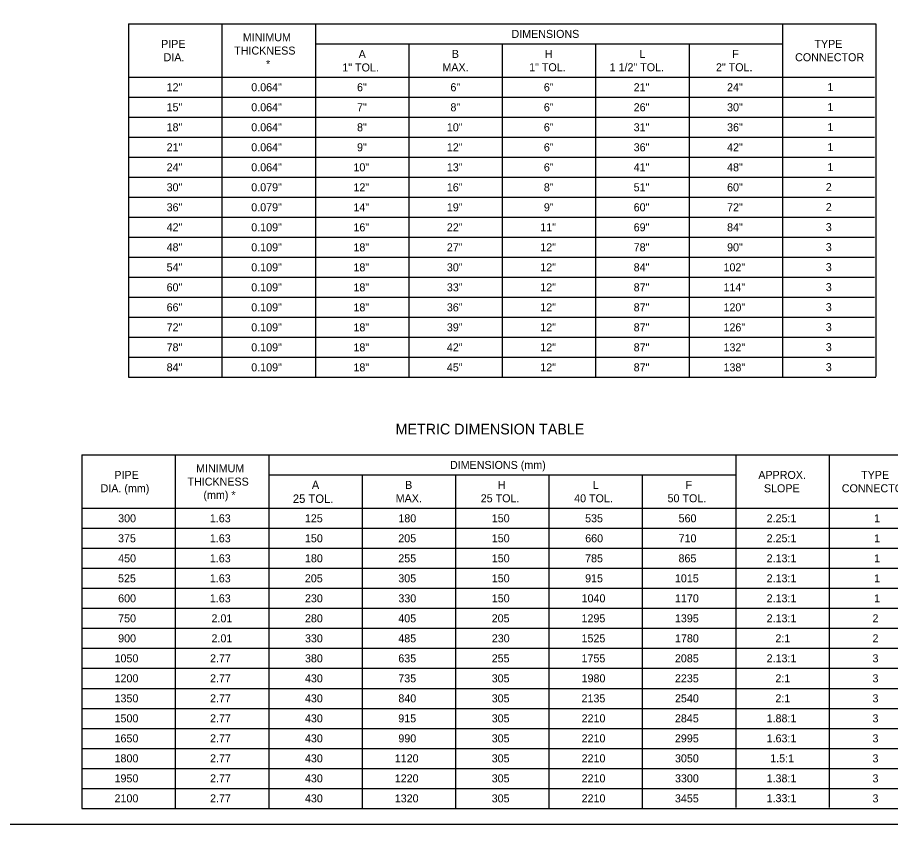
# Model space of a CAD drawing. Extents: x 49991.4 to 50021, y 49987.6 to 50011.4.
# Drawn here: x 50006.92 to 50013.46, y 49987.8 to 49993.85 of the extents above; entities that cross this region are included whole.
import ezdxf

# ---------------------------------------------------------------- set-up
doc = ezdxf.new("R2010")
doc.units = 0
doc.layers.add('Level 1', color=7, linetype='Continuous')
doc.layers.add('Level 2', color=7, linetype='Continuous')

msp = doc.modelspace()

# ---------------------------------------------------------------- linework, layer by layer
at = {"layer": 'Level 1'}
msp.add_lwpolyline([(49999.3835, 49998.9992), (50016.7501, 49998.9992), (50016.7501, 49987.7988), (49999.3835, 49987.7988)], close=True, dxfattribs=at)
at = {"layer": 'Level 2'}
for p, q in [((50007.7477, 49993.802), (50007.7477, 49991.152)), ((50007.7477, 49993.802), (50013.3477, 49993.802)), ((50008.4477, 49993.802), (50008.4477, 49991.152)), ((50009.1477, 49993.802), (50009.1477, 49991.152)), ((50012.6477, 49993.802), (50012.6477, 49991.1586)), ((50013.3477, 49993.802), (50013.3477, 49991.1586)), ((50009.1477, 49993.652), (50012.6477, 49993.652)), ((50009.8477, 49993.652), (50009.8477, 49991.152)), ((50010.5477, 49993.652), (50010.5477, 49991.152)), ((50011.2477, 49993.652), (50011.2477, 49991.152)), ((50011.9477, 49993.652), (50011.9477, 49991.152)), ((50007.7477, 49993.402), (50013.3377, 49993.402)), ((50007.7477, 49993.252), (50013.3377, 49993.252)), ((50007.7477, 49993.102), (50013.3377, 49993.102)), ((50007.7477, 49992.952), (50013.3377, 49992.952)), ((50007.7477, 49992.802), (50013.3377, 49992.802)), ((50007.7477, 49992.652), (50013.3377, 49992.652)), ((50007.7477, 49992.502), (50013.3377, 49992.502)), ((50007.7477, 49992.352), (50013.3377, 49992.352)), ((50007.7477, 49992.202), (50013.3377, 49992.202)), ((50007.7477, 49992.052), (50013.3377, 49992.052)), ((50007.7477, 49991.902), (50013.3377, 49991.902)), ((50007.7477, 49991.752), (50013.3377, 49991.752)), ((50007.7477, 49991.602), (50013.3377, 49991.602)), ((50007.7477, 49991.452), (50013.3377, 49991.452)), ((50007.7477, 49991.302), (50013.3377, 49991.302)), ((50007.7477, 49991.152), (50013.3477, 49991.152)), ((50007.3977, 49990.5701), (50007.3977, 49987.9201)), ((50007.3977, 49990.5701), (50013.6977, 49990.5701)), ((50008.0977, 49990.5701), (50008.0977, 49987.9201)), ((50008.7977, 49990.5701), (50008.7977, 49987.9201)), ((50012.2977, 49990.5701), (50012.2977, 49987.9267)), ((50012.9977, 49990.5701), (50012.9977, 49987.9267)), ((50008.7977, 49990.4201), (50012.2977, 49990.4201)), ((50009.4977, 49990.4201), (50009.4977, 49987.9201)), ((50010.1977, 49990.4201), (50010.1977, 49987.9201)), ((50010.8977, 49990.4201), (50010.8977, 49987.9201)), ((50011.5977, 49990.4201), (50011.5977, 49987.9201)), ((50007.3977, 49990.1701), (50013.6977, 49990.1701)), ((50007.3977, 49990.0201), (50013.6977, 49990.0201)), ((50007.3977, 49989.8701), (50013.6977, 49989.8701)), ((50007.3977, 49989.7201), (50013.6977, 49989.7201)), ((50007.3977, 49989.5701), (50013.6977, 49989.5701)), ((50007.3977, 49989.4201), (50013.6977, 49989.4201)), ((50007.3977, 49989.2701), (50013.6977, 49989.2701)), ((50007.3977, 49989.1201), (50013.6977, 49989.1201)), ((50007.3977, 49988.9701), (50013.6977, 49988.9701)), ((50007.3977, 49988.8201), (50013.6977, 49988.8201)), ((50007.3977, 49988.6701), (50013.6977, 49988.6701)), ((50007.3977, 49988.5201), (50013.6977, 49988.5201)), ((50007.3977, 49988.3701), (50013.6977, 49988.3701)), ((50007.3977, 49988.2201), (50013.6977, 49988.2201)), ((50007.3977, 49988.0701), (50013.6977, 49988.0701)), ((50007.3977, 49987.9201), (50013.6977, 49987.9201))]:
    msp.add_line(p, q, dxfattribs=at)

# ---------------------------------------------------------------- texts
for s, height, p in [('MINIMUM', 0.06, (50008.6036, 49993.672)), ('DIMENSIONS', 0.06, (50010.6172, 49993.697)), ('PIPE', 0.06, (50007.9914, 49993.622)), ('THICKNESS', 0.06, (50008.5392, 49993.572)), ('TYPE', 0.06, (50012.8875, 49993.622)), ('DIA.', 0.06, (50008.0103, 49993.522)), ('A', 0.06, (50009.4719, 49993.5455)), ('B', 0.06, (50010.17, 49993.547)), ('H', 0.06, (50010.8657, 49993.547)), ('L', 0.06, (50011.5765, 49993.547)), ('F', 0.06, (50012.2715, 49993.547)), ('CONNECTOR', 0.06, (50012.7426, 49993.522)), ('*', 0.06, (50008.7778, 49993.472)), ('1" TOL.', 0.06, (50009.3495, 49993.4455)), ('MAX.', 0.06, (50010.0995, 49993.447)), ('1" TOL.', 0.06, (50010.7495, 49993.447)), ('1 1/2" TOL.', 0.06, (50011.3527, 49993.447)), ('2" TOL.', 0.06, (50012.1495, 49993.447)), ('12"', 0.06, (50008.0328, 49993.297)), ('0.064"', 0.06, (50008.6671, 49993.297)), ('6"', 0.06, (50009.4597, 49993.297)), ('6"', 0.06, (50010.1597, 49993.297)), ('6"', 0.06, (50010.8597, 49993.297)), ('21"', 0.06, (50011.5328, 49993.297)), ('24"', 0.06, (50012.2328, 49993.297)), ('1', 0.06, (50012.9847, 49993.2984)), ('15"', 0.06, (50008.0328, 49993.147)), ('0.064"', 0.06, (50008.6671, 49993.147)), ('7"', 0.06, (50009.4597, 49993.147)), ('8"', 0.06, (50010.1597, 49993.147)), ('6"', 0.06, (50010.8597, 49993.147)), ('26"', 0.06, (50011.5328, 49993.147)), ('30"', 0.06, (50012.2328, 49993.147)), ('1', 0.06, (50012.9847, 49993.1484)), ('18"', 0.06, (50008.0328, 49992.997)), ('0.064"', 0.06, (50008.6671, 49992.997)), ('8"', 0.06, (50009.4597, 49992.997)), ('10"', 0.06, (50010.1328, 49992.997)), ('6"', 0.06, (50010.8597, 49992.997)), ('31"', 0.06, (50011.5328, 49992.997)), ('36"', 0.06, (50012.2328, 49992.997)), ('1', 0.06, (50012.9847, 49992.9984)), ('21"', 0.06, (50008.0328, 49992.847)), ('0.064"', 0.06, (50008.6671, 49992.847)), ('9"', 0.06, (50009.4597, 49992.847)), ('12"', 0.06, (50010.1328, 49992.847)), ('6"', 0.06, (50010.8597, 49992.847)), ('36"', 0.06, (50011.5328, 49992.847)), ('42"', 0.06, (50012.2328, 49992.847)), ('1', 0.06, (50012.9847, 49992.8484)), ('24"', 0.06, (50008.0328, 49992.697)), ('0.064"', 0.06, (50008.6671, 49992.697)), ('10"', 0.06, (50009.4328, 49992.697)), ('13"', 0.06, (50010.1328, 49992.697)), ('6"', 0.06, (50010.8597, 49992.697)), ('41"', 0.06, (50011.5328, 49992.697)), ('48"', 0.06, (50012.2328, 49992.697)), ('1', 0.06, (50012.9847, 49992.6984)), ('30"', 0.06, (50008.0328, 49992.547)), ('0.079"', 0.06, (50008.6671, 49992.547)), ('12"', 0.06, (50009.4328, 49992.547)), ('16"', 0.06, (50010.1328, 49992.547)), ('8"', 0.06, (50010.8597, 49992.547)), ('51"', 0.06, (50011.5328, 49992.547)), ('60"', 0.06, (50012.2328, 49992.547)), ('2', 0.06, (50012.9725, 49992.5484)), ('36"', 0.06, (50008.0328, 49992.397)), ('0.079"', 0.06, (50008.6671, 49992.397)), ('14"', 0.06, (50009.4328, 49992.397)), ('19"', 0.06, (50010.1328, 49992.397)), ('9"', 0.06, (50010.8597, 49992.397)), ('60"', 0.06, (50011.5328, 49992.397)), ('72"', 0.06, (50012.2328, 49992.397)), ('2', 0.06, (50012.9725, 49992.3984)), ('42"', 0.06, (50008.0328, 49992.247)), ('0.109"', 0.06, (50008.6671, 49992.247)), ('16"', 0.06, (50009.4328, 49992.247)), ('22"', 0.06, (50010.1328, 49992.247)), ('11"', 0.06, (50010.8328, 49992.247)), ('69"', 0.06, (50011.5328, 49992.247)), ('84"', 0.06, (50012.2328, 49992.247)), ('3', 0.06, (50012.9725, 49992.2484)), ('48"', 0.06, (50008.0328, 49992.097)), ('0.109"', 0.06, (50008.6671, 49992.097)), ('18"', 0.06, (50009.4328, 49992.097)), ('27"', 0.06, (50010.1328, 49992.097)), ('12"', 0.06, (50010.8328, 49992.097)), ('78"', 0.06, (50011.5328, 49992.097)), ('90"', 0.06, (50012.2328, 49992.097)), ('3', 0.06, (50012.9725, 49992.0984)), ('54"', 0.06, (50008.0328, 49991.947)), ('0.109"', 0.06, (50008.6671, 49991.947)), ('18"', 0.06, (50009.4328, 49991.947)), ('30"', 0.06, (50010.1328, 49991.947)), ('12"', 0.06, (50010.8328, 49991.947)), ('84"', 0.06, (50011.5328, 49991.947)), ('102"', 0.06, (50012.2059, 49991.947)), ('3', 0.06, (50012.9725, 49991.9484)), ('60"', 0.06, (50008.0328, 49991.797)), ('0.109"', 0.06, (50008.6671, 49991.797)), ('18"', 0.06, (50009.4328, 49991.797)), ('33"', 0.06, (50010.1328, 49991.797)), ('12"', 0.06, (50010.8328, 49991.797)), ('87"', 0.06, (50011.5328, 49991.797)), ('114"', 0.06, (50012.2059, 49991.797)), ('3', 0.06, (50012.9725, 49991.7984)), ('66"', 0.06, (50008.0328, 49991.647)), ('0.109"', 0.06, (50008.6671, 49991.647)), ('18"', 0.06, (50009.4328, 49991.647)), ('36"', 0.06, (50010.1328, 49991.647)), ('12"', 0.06, (50010.8328, 49991.647)), ('87"', 0.06, (50011.5328, 49991.647)), ('120"', 0.06, (50012.2059, 49991.647)), ('3', 0.06, (50012.9725, 49991.6484)), ('72"', 0.06, (50008.0328, 49991.497)), ('0.109"', 0.06, (50008.6671, 49991.497)), ('18"', 0.06, (50009.4328, 49991.497)), ('39"', 0.06, (50010.1328, 49991.497)), ('12"', 0.06, (50010.8328, 49991.497)), ('87"', 0.06, (50011.5328, 49991.497)), ('126"', 0.06, (50012.2059, 49991.497)), ('3', 0.06, (50012.9725, 49991.4984)), ('78"', 0.06, (50008.0328, 49991.347)), ('0.109"', 0.06, (50008.6671, 49991.347)), ('18"', 0.06, (50009.4328, 49991.347)), ('42"', 0.06, (50010.1328, 49991.347)), ('12"', 0.06, (50010.8328, 49991.347)), ('87"', 0.06, (50011.5328, 49991.347)), ('132"', 0.06, (50012.2059, 49991.347)), ('3', 0.06, (50012.9725, 49991.3484)), ('84"', 0.06, (50008.0328, 49991.197)), ('0.109"', 0.06, (50008.6671, 49991.197)), ('18"', 0.06, (50009.4328, 49991.197)), ('45"', 0.06, (50010.1328, 49991.197)), ('12"', 0.06, (50010.8328, 49991.197)), ('87"', 0.06, (50011.5328, 49991.197)), ('138"', 0.06, (50012.2059, 49991.197)), ('3', 0.06, (50012.9725, 49991.1984)), ('METRIC DIMENSION TABLE', 0.08, (50009.7483, 49990.7242)), ('MINIMUM', 0.06, (50008.2536, 49990.4401)), ('DIMENSIONS (mm)', 0.06, (50010.1563, 49990.4651)), ('PIPE', 0.06, (50007.6414, 49990.3901)), ('APPROX.', 0.06, (50012.4669, 49990.3901)), ('TYPE', 0.06, (50013.2375, 49990.3901)), ('THICKNESS', 0.06, (50008.1892, 49990.3401)), ('A', 0.063, (50009.1206, 49990.3136)), ('B', 0.06, (50009.82, 49990.3151)), ('H', 0.06, (50010.5157, 49990.3151)), ('L', 0.06, (50011.2265, 49990.3151)), ('F', 0.06, (50011.9215, 49990.3151)), ('DIA. (mm)', 0.06, (50007.538, 49990.2901)), ('(mm) *', 0.06, (50008.3089, 49990.2401)), ('SLOPE', 0.06, (50012.5089, 49990.2901)), ('CONNECTOR', 0.06, (50013.0926, 49990.2901)), ('25 TOL.', 0.063, (50008.9788, 49990.2106)), ('MAX.', 0.06, (50009.7495, 49990.2151)), ('25 TOL.', 0.06, (50010.3868, 49990.2151)), ('40 TOL.', 0.06, (50011.0868, 49990.2151)), ('50 TOL.', 0.06, (50011.7868, 49990.2151)), ('300', 0.06, (50007.6695, 49990.0651)), ('1.63', 0.06, (50008.3568, 49990.0651)), ('125', 0.06, (50009.0689, 49990.0651)), ('180', 0.06, (50009.7695, 49990.0651)), ('150', 0.06, (50010.4695, 49990.0651)), ('535', 0.06, (50011.1689, 49990.0651)), ('560', 0.06, (50011.8695, 49990.0651)), ('2.25:1', 0.06, (50012.5291, 49990.0651)), ('1', 0.06, (50013.3347, 49990.0651)), ('375', 0.06, (50007.6689, 49989.9151)), ('1.63', 0.06, (50008.3568, 49989.9151)), ('150', 0.06, (50009.0695, 49989.9151)), ('205', 0.06, (50009.7689, 49989.9151)), ('150', 0.06, (50010.4695, 49989.9151)), ('660', 0.06, (50011.1695, 49989.9151)), ('710', 0.06, (50011.8695, 49989.9151)), ('2.25:1', 0.06, (50012.5291, 49989.9151)), ('1', 0.06, (50013.3347, 49989.9151)), ('450', 0.06, (50007.6695, 49989.7651)), ('1.63', 0.06, (50008.3568, 49989.7651)), ('180', 0.06, (50009.0695, 49989.7651)), ('255', 0.06, (50009.7689, 49989.7651)), ('150', 0.06, (50010.4695, 49989.7651)), ('785', 0.06, (50011.1689, 49989.7651)), ('865', 0.06, (50011.8689, 49989.7651)), ('2.13:1', 0.06, (50012.5291, 49989.7651)), ('1', 0.06, (50013.3347, 49989.7651)), ('525', 0.06, (50007.6689, 49989.6151)), ('1.63', 0.06, (50008.3568, 49989.6151)), ('205', 0.06, (50009.0689, 49989.6151)), ('305', 0.06, (50009.7689, 49989.6151)), ('150', 0.06, (50010.4695, 49989.6151)), ('915', 0.06, (50011.1689, 49989.6151)), ('1015', 0.06, (50011.842, 49989.6151)), ('2.13:1', 0.06, (50012.5291, 49989.6151)), ('1', 0.06, (50013.3347, 49989.6151)), ('600', 0.06, (50007.6695, 49989.4651)), ('1.63', 0.06, (50008.3568, 49989.4651)), ('230', 0.06, (50009.0695, 49989.4651)), ('330', 0.06, (50009.7695, 49989.4651)), ('150', 0.06, (50010.4695, 49989.4651)), ('1040', 0.06, (50011.1425, 49989.4651)), ('1170', 0.06, (50011.8425, 49989.4651)), ('2.13:1', 0.06, (50012.5291, 49989.4651)), ('1', 0.06, (50013.3347, 49989.4651)), ('750', 0.06, (50007.6695, 49989.3151)), ('2.01', 0.06, (50008.3691, 49989.3151)), ('280', 0.06, (50009.0695, 49989.3151)), ('405', 0.06, (50009.7689, 49989.3151)), ('205', 0.06, (50010.4689, 49989.3151)), ('1295', 0.06, (50011.142, 49989.3151)), ('1395', 0.06, (50011.842, 49989.3151)), ('2.13:1', 0.06, (50012.5291, 49989.3151)), ('2', 0.06, (50013.3225, 49989.3151)), ('900', 0.06, (50007.6695, 49989.1651)), ('2.01', 0.06, (50008.3691, 49989.1651)), ('330', 0.06, (50009.0695, 49989.1651)), ('485', 0.06, (50009.7689, 49989.1651)), ('230', 0.06, (50010.4695, 49989.1651)), ('1525', 0.06, (50011.142, 49989.1651)), ('1780', 0.06, (50011.8425, 49989.1651)), ('2:1', 0.06, (50012.5948, 49989.1651)), ('2', 0.06, (50013.3225, 49989.1651)), ('1050', 0.06, (50007.6425, 49989.0151)), ('2.77', 0.06, (50008.3582, 49989.0151)), ('380', 0.06, (50009.0695, 49989.0151)), ('635', 0.06, (50009.7689, 49989.0151)), ('255', 0.06, (50010.4689, 49989.0151)), ('1755', 0.06, (50011.142, 49989.0151)), ('2085', 0.06, (50011.842, 49989.0151)), ('2.13:1', 0.06, (50012.5291, 49989.0151)), ('3', 0.06, (50013.3225, 49989.0151)), ('1200', 0.06, (50007.6425, 49988.8651)), ('2.77', 0.06, (50008.3582, 49988.8651)), ('430', 0.06, (50009.0695, 49988.8651)), ('735', 0.06, (50009.7689, 49988.8651)), ('305', 0.06, (50010.4689, 49988.8651)), ('1980', 0.06, (50011.1425, 49988.8651)), ('2235', 0.06, (50011.842, 49988.8651)), ('2:1', 0.06, (50012.5948, 49988.8651)), ('3', 0.06, (50013.3225, 49988.8651)), ('1350', 0.06, (50007.6425, 49988.7151)), ('2.77', 0.06, (50008.3582, 49988.7151)), ('430', 0.06, (50009.0695, 49988.7151)), ('840', 0.06, (50009.7695, 49988.7151)), ('305', 0.06, (50010.4689, 49988.7151)), ('2135', 0.06, (50011.142, 49988.7151)), ('2540', 0.06, (50011.8425, 49988.7151)), ('2:1', 0.06, (50012.5948, 49988.7151)), ('3', 0.06, (50013.3225, 49988.7151)), ('1500', 0.06, (50007.6425, 49988.5651)), ('2.77', 0.06, (50008.3582, 49988.5651)), ('430', 0.06, (50009.0695, 49988.5651)), ('915', 0.06, (50009.7689, 49988.5651)), ('305', 0.06, (50010.4689, 49988.5651)), ('2210', 0.06, (50011.1425, 49988.5651)), ('2845', 0.06, (50011.842, 49988.5651)), ('1.88:1', 0.06, (50012.5291, 49988.5651)), ('3', 0.06, (50013.3225, 49988.5651)), ('1650', 0.06, (50007.6425, 49988.4151)), ('2.77', 0.06, (50008.3582, 49988.4151)), ('430', 0.06, (50009.0695, 49988.4151)), ('990', 0.06, (50009.7695, 49988.4151)), ('305', 0.06, (50010.4689, 49988.4151)), ('2210', 0.06, (50011.1425, 49988.4151)), ('2995', 0.06, (50011.842, 49988.4151)), ('1.63:1', 0.06, (50012.5291, 49988.4151)), ('3', 0.06, (50013.3225, 49988.4151)), ('1800', 0.06, (50007.6425, 49988.2651)), ('2.77', 0.06, (50008.3582, 49988.2651)), ('430', 0.06, (50009.0695, 49988.2651)), ('1120', 0.06, (50009.7425, 49988.2651)), ('305', 0.06, (50010.4689, 49988.2651)), ('2210', 0.06, (50011.1425, 49988.2651)), ('3050', 0.06, (50011.8425, 49988.2651)), ('1.5:1', 0.06, (50012.5561, 49988.2651)), ('3', 0.06, (50013.3225, 49988.2651)), ('1950', 0.06, (50007.6425, 49988.1151)), ('2.77', 0.06, (50008.3582, 49988.1151)), ('430', 0.06, (50009.0695, 49988.1151)), ('1220', 0.06, (50009.7425, 49988.1151)), ('305', 0.06, (50010.4689, 49988.1151)), ('2210', 0.06, (50011.1425, 49988.1151)), ('3300', 0.06, (50011.8425, 49988.1151)), ('1.38:1', 0.06, (50012.5291, 49988.1151)), ('3', 0.06, (50013.3225, 49988.1151)), ('2100', 0.06, (50007.6425, 49987.9651)), ('2.77', 0.06, (50008.3582, 49987.9651)), ('430', 0.06, (50009.0695, 49987.9651)), ('1320', 0.06, (50009.7425, 49987.9651)), ('305', 0.06, (50010.4689, 49987.9651)), ('2210', 0.06, (50011.1425, 49987.9651)), ('3455', 0.06, (50011.842, 49987.9651)), ('1.33:1', 0.06, (50012.5291, 49987.9665)), ('3', 0.06, (50013.3225, 49987.9651))]:
    msp.add_text(s, height=height, dxfattribs=at).set_placement(p)

doc.saveas('drawing.dxf')
